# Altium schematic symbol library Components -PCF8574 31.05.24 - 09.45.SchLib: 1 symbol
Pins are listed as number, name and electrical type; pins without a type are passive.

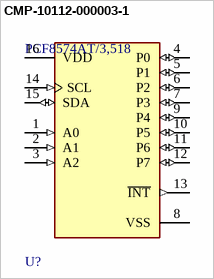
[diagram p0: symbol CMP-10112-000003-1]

## CMP-10112-000003-1
designator U?, comment PCF8574AT/3,518
IC I/O EXPANDER I2C 8B 16SOIC; Manufacturer: NXP Semiconductors; Interface: I2C,SMBus; Frequency: 100kHz; Nominal Supply Current: 40uA; Max Supply Voltage: 6V; Number Of I/Os: 8; Max Junction Temp: +125°C; Min Supply Voltage: 2.5V; Standoff Height: 0.1mm
footprint FP-SOT162-1-IPC_B
footprint FP-SOT162-1-IPC_A
footprint FP-SOT162-1-MFG
footprint FP-SOT162-1-IPC_C
pins: 1 A0 (in), 2 A1 (in), 3 A2 (in), 4 P0 (io), 5 P1 (io), 6 P2 (io), 7 P3 (io), 8 VSS (power), 9 P4 (io), 10 P5 (io), 11 P6 (io), 12 P7 (io), 13 ~{INT} (out), 14 SCL (in), 15 SDA (io), 16 VDD (power)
